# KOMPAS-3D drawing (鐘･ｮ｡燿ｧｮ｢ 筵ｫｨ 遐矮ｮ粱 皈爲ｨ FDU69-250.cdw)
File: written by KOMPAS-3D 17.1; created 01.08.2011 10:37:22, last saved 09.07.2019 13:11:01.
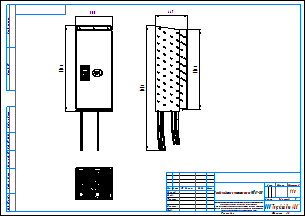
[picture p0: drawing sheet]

Title block, sheet 1: name: Преобразователи частоты серии FDU69-250; scale: 1:10; sheets: 1; sheet format: A3; stored path: \\adlc.lan\data\АДЛ_ПКД\3D-модели\Поставщики\Оборудование Emotron\Преобразователи частоты\Серия FDU 2.0\KOMPAS 2D\Преобразователи частоты серии FDU69-250.cdw

Views: Спереди 1
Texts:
  Рама для чертежей
  Лит-Масса-Масштаб
  Материал-Предприятие
  Масштаб
  Изм.
  Лист
  № докум.
  Подп.
  Дата
  Лит.
  Разраб.
  Пров.
  Т.контр.
  Листов
  Внимание! Данный продукт является объектом авторского права ООО «Торговый Дом АДЛ».
  Запрещается изменение, копирование, распространение
  (в том числе путем копирования на другие сайты и ресурсы в Интернете)
  или любое иное использование информации и объектов без предварительного
  согласия правообладателя (ООО «Торговый Дом АДЛ»).
  Н.контр.
  Утв.
  ООО "Торговый дом АДЛ"
  Изменение
  Номер документа
  Подпись
  Обозначение документа
  Наименование изделия
  Масса изделия по ГОСТ 2.109-73
  Порядковый номер листа
  Общее количество листов в документе
  Характер работы, выполненной лицом, подписавшим документ
  Наименование или индекс предприятия, выпускающего документ
  Инв. № подл.
  Подп. и дата
  Взам. инв. №
  Инв. № дубл.
  Инвентарный номер подлинника по ГОСТ 2.501-68
  Подпись принявшего подлинник в отдел технической документации
  Инвентарный номер подлинника, взамен которого выпущен данный подлинник
  Инвентарный номер дубликата по ГОСТ 2.502-68
  Подпись принявшего дубликат в отдел технической документации
  Справ. №
  Перв. примен.
  Обозначение документа, взамен или на основании которого выпущен данный документ
  Обозначение документа, в котором впервые записан данный документ
  Подпись лица, копировавшего чертеж
  Обозначение формата листа
  !Рама для чертежа
Dimensions and other numbers on the sheet: 1176; 500; 1718; 449; 1100; 1:10; 1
